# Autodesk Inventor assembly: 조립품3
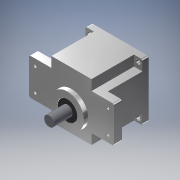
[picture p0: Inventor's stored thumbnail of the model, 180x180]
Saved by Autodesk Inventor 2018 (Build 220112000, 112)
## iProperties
Created: 2020-07
Part Number: 조립품3
Material: 일반
Document SubType Name: Assembly
Designer: Admin
Author: Admin
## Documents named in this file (10)
- C:\Users\Admin\Desktop\700707V1009\조립품3.iam
- C:\Users\Admin\Desktop\700707V1009\부품.ipt
- C:\Users\Admin\Desktop\700707V1009\커버.ipt
- C:\Users\Admin\Desktop\700707V1009\메인 축.ipt
- C:\Users\Admin\Desktop\700707V1009\베어링 608.ipt
- C:\Users\Admin\Desktop\700707V1009\서브 축.ipt
- C:\Users\Admin\Desktop\700707V1009\베어링 6003.ipt
- C:\Users\Admin\Desktop\700707V1009\볼트 M4.ipt
- C:\Users\Admin\Desktop\700707V1009\오일 실 17 32 8.ipt
- C:\Users\Admin\Desktop\700707V1009\오일 실 8 22 7.ipt
